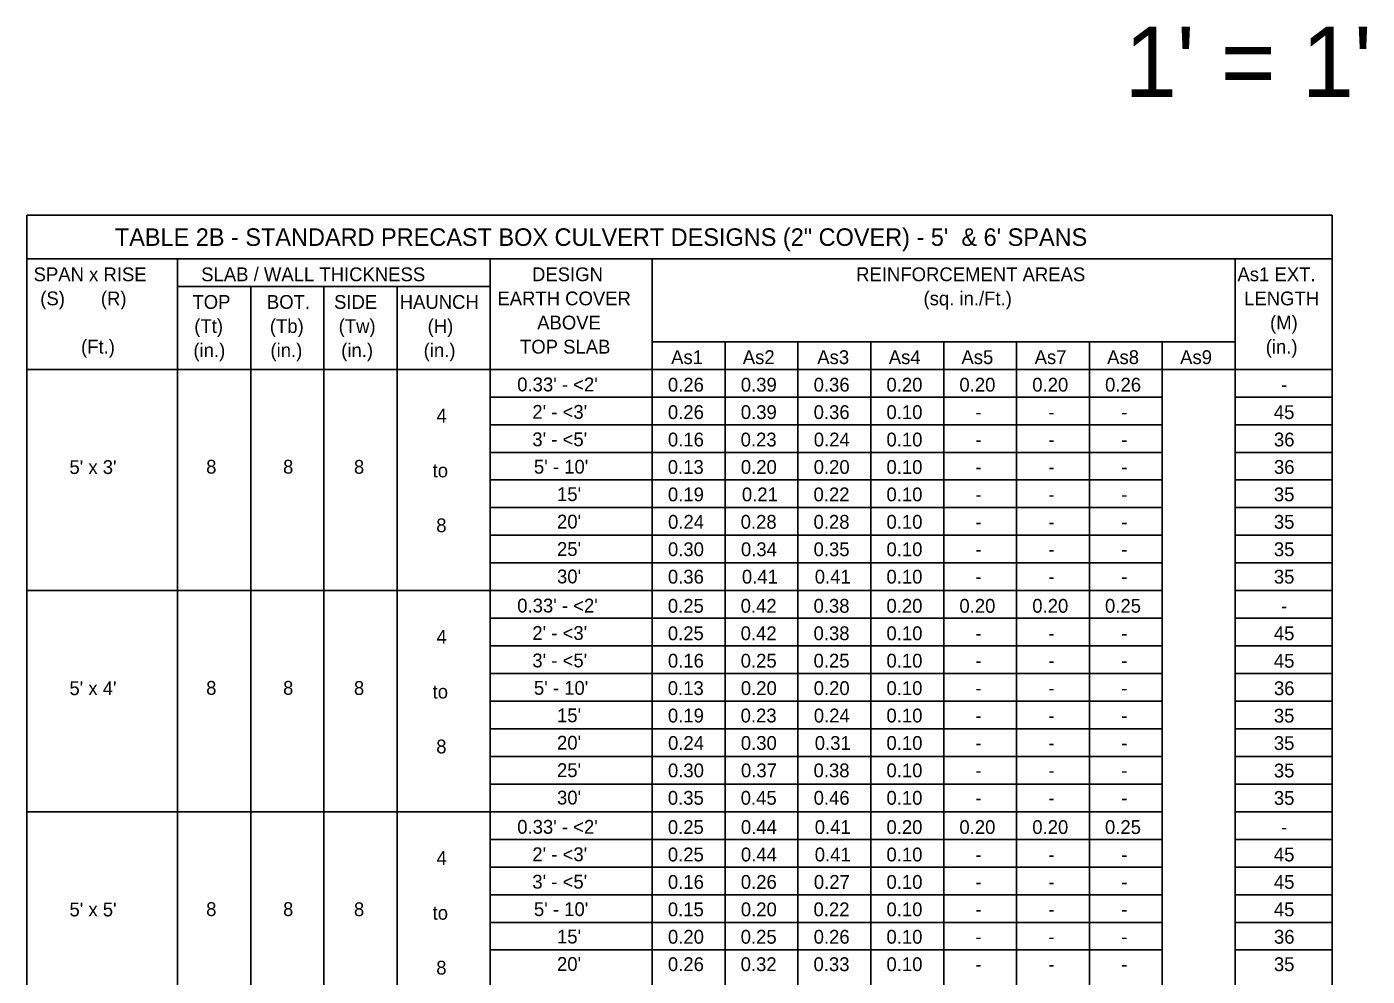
# Model space of a CAD drawing. Extents: x 10340.93 to 10343.14, y 76399.51 to 76400.59.
# Drawn here: x 10341.579 to 10342.189, y 76400.153 to 76400.586 of the extents above; entities that cross this region are included whole.
import ezdxf

# ---------------------------------------------------------------- set-up
doc = ezdxf.new("R2010")
doc.units = 0
doc.layers.add('AdhocPoint_dp', color=7, linetype='Continuous')
doc.layers.add('PlotBorder_dp', color=7, linetype='Continuous')

msp = doc.modelspace()

# ---------------------------------------------------------------- linework, layer by layer
at = {"layer": 'PlotBorder_dp'}
for p, q in [((10341.57868, 76400.49971), (10341.57868, 76399.72389)), ((10341.57868, 76400.49971), (10342.17342, 76400.49971)), ((10342.17342, 76400.49971), (10342.17342, 76399.72389)), ((10341.57868, 76400.47984), (10342.17342, 76400.47984)), ((10341.64732, 76400.47984), (10341.64732, 76399.72389)), ((10341.78976, 76400.47984), (10341.78976, 76399.72389)), ((10341.86364, 76400.47984), (10341.86364, 76399.72389)), ((10342.12923, 76400.47984), (10342.12923, 76399.72389)), ((10341.64732, 76400.46724), (10341.78976, 76400.46724)), ((10341.68068, 76400.46724), (10341.68068, 76399.72389)), ((10341.71404, 76400.46724), (10341.71404, 76399.72389)), ((10341.7474, 76400.46724), (10341.7474, 76399.72389)), ((10341.86364, 76400.44209), (10342.12923, 76400.44209)), ((10341.89684, 76400.44209), (10341.89684, 76399.72389)), ((10341.93004, 76400.44209), (10341.93004, 76399.72389)), ((10341.96324, 76400.44209), (10341.96324, 76399.72389)), ((10341.99644, 76400.44209), (10341.99644, 76399.72389)), ((10342.02963, 76400.44209), (10342.02963, 76399.72389)), ((10342.02963, 76400.44209), (10342.02963, 76399.72389)), ((10342.06283, 76400.44209), (10342.06283, 76399.72389)), ((10342.09603, 76400.44209), (10342.09603, 76399.72389)), ((10341.57868, 76400.42949), (10342.17342, 76400.42949)), ((10341.78976, 76400.41689), (10342.09603, 76400.41689)), ((10342.12923, 76400.41689), (10342.17342, 76400.41689)), ((10341.78976, 76400.40429), (10342.09603, 76400.40429)), ((10342.12923, 76400.40429), (10342.17342, 76400.40429)), ((10341.78976, 76400.39169), (10342.09603, 76400.39169)), ((10342.12923, 76400.39169), (10342.17342, 76400.39169)), ((10341.78976, 76400.37909), (10342.09603, 76400.37909)), ((10342.12923, 76400.37909), (10342.17342, 76400.37909)), ((10341.78976, 76400.36649), (10342.09603, 76400.36649)), ((10342.12923, 76400.36649), (10342.17342, 76400.36649)), ((10341.78976, 76400.35389), (10342.09603, 76400.35389)), ((10342.12923, 76400.35389), (10342.17342, 76400.35389)), ((10341.78976, 76400.34129), (10342.09603, 76400.34129)), ((10342.12923, 76400.34129), (10342.17342, 76400.34129)), ((10341.57868, 76400.32869), (10342.09603, 76400.32869)), ((10342.12923, 76400.32869), (10342.17342, 76400.32869)), ((10341.78976, 76400.31609), (10342.09603, 76400.31609)), ((10342.12923, 76400.31609), (10342.17342, 76400.31609)), ((10341.78976, 76400.30349), (10342.09603, 76400.30349)), ((10342.12923, 76400.30349), (10342.17342, 76400.30349)), ((10341.78976, 76400.29089), (10342.09603, 76400.29089)), ((10342.12923, 76400.29089), (10342.17342, 76400.29089)), ((10341.78976, 76400.27829), (10342.09603, 76400.27829)), ((10342.12923, 76400.27829), (10342.17342, 76400.27829)), ((10341.78976, 76400.26569), (10342.09603, 76400.26569)), ((10342.12923, 76400.26569), (10342.17342, 76400.26569)), ((10341.78976, 76400.25309), (10342.09603, 76400.25309)), ((10342.12923, 76400.25309), (10342.17342, 76400.25309)), ((10341.78976, 76400.24049), (10342.09603, 76400.24049)), ((10342.12923, 76400.24049), (10342.17342, 76400.24049)), ((10341.57868, 76400.22789), (10342.09603, 76400.22789)), ((10342.12923, 76400.22789), (10342.17342, 76400.22789)), ((10341.78976, 76400.21529), (10342.09603, 76400.21529)), ((10342.12923, 76400.21529), (10342.17342, 76400.21529)), ((10341.78976, 76400.20269), (10342.09603, 76400.20269)), ((10342.12923, 76400.20269), (10342.17342, 76400.20269)), ((10341.78976, 76400.19009), (10342.09603, 76400.19009)), ((10342.12923, 76400.19009), (10342.17342, 76400.19009)), ((10341.78976, 76400.17749), (10342.09603, 76400.17749)), ((10342.12923, 76400.17749), (10342.17342, 76400.17749)), ((10341.78976, 76400.16489), (10342.09603, 76400.16489)), ((10342.12923, 76400.16489), (10342.17342, 76400.16489))]:
    msp.add_line(p, q, dxfattribs=at)

# ---------------------------------------------------------------- texts
at = {"layer": 'AdhocPoint_dp'}
for s, height, p in [("1' = 1'", 0.032, (10342.07883, 76400.55363)), ('TABLE 2B - STANDARD PRECAST BOX CULVERT DESIGNS (2" COVER) - 5\'  & 6\' SPANS', 0.008, (10341.6188, 76400.48578)), ('SLAB / WALL THICKNESS', 0.0063, (10341.65814, 76400.46968)), ('As1', 0.0063, (10341.87226, 76400.43192)), ('As2', 0.0063, (10341.90489, 76400.43192)), ('As3', 0.0063, (10341.93883, 76400.43192)), ('As4', 0.0063, (10341.97141, 76400.43192)), ('As5', 0.0063, (10342.00451, 76400.43192)), ('As7', 0.0063, (10342.03786, 76400.43192)), ('As8', 0.0063, (10342.0709, 76400.43192)), ('As9', 0.0063, (10342.10415, 76400.43192)), ("5' x 3'", 0.0063, (10341.5981, 76400.38182)), ("5' x 4'", 0.0063, (10341.59809, 76400.28104)), ("5' x 5'", 0.0063, (10341.59811, 76400.18021))]:
    msp.add_text(s, height=height, dxfattribs=at).set_placement(p)
at = {"layer": 'PlotBorder_dp'}
for s, p in [('SPAN x RISE', (10341.58177, 76400.46969)), ('DESIGN', (10341.80886, 76400.46969)), ('REINFORCEMENT AREAS', (10341.95654, 76400.46969)), ('(S)       (R)', (10341.58481, 76400.45869)), ('EARTH COVER', (10341.79307, 76400.45869)), ('(sq. in./Ft.)', (10341.98723, 76400.45869)), ('TOP', (10341.65414, 76400.45708)), ('BOT.', (10341.68807, 76400.45708)), ('SIDE', (10341.71867, 76400.45708)), ('HAUNCH', (10341.74856, 76400.45708)), ('(Tt)', (10341.65498, 76400.44608)), ('(Tb)', (10341.68941, 76400.44608)), ('(Tw)', (10341.72077, 76400.44608)), ('(H)', (10341.7613, 76400.44608)), ('ABOVE', (10341.81121, 76400.44769)), ('(Ft.)', (10341.60339, 76400.43669)), ('(in.)', (10341.65459, 76400.43508)), ('(in.)', (10341.68969, 76400.43508)), ('(in.)', (10341.72192, 76400.43508)), ('(in.)', (10341.75949, 76400.43508)), ('TOP SLAB', (10341.80338, 76400.43669)), ("0.33' - <2'", (10341.80212, 76400.41948)), ('0.26', (10341.87078, 76400.41937)), ('0.39', (10341.90398, 76400.41937)), ('0.36', (10341.93718, 76400.41937)), ('0.20', (10341.97035, 76400.41937)), ('0.20', (10342.00358, 76400.41937)), ('0.20', (10342.03679, 76400.41937)), ('0.26', (10342.06996, 76400.41937)), ('-', (10342.15015, 76400.41937)), ('4', (10341.76534, 76400.40529)), ("2' - <3'", (10341.80901, 76400.40698)), ('0.26', (10341.87078, 76400.40687)), ('0.39', (10341.90398, 76400.40687)), ('0.36', (10341.93718, 76400.40687)), ('0.10', (10341.97035, 76400.40687)), ('-', (10342.01091, 76400.40687)), ('-', (10342.04412, 76400.40687)), ('-', (10342.0773, 76400.40687)), ('45', (10342.14685, 76400.40687)), ("3' - <5'", (10341.80901, 76400.39448)), ('0.16', (10341.87078, 76400.39437)), ('0.23', (10341.90391, 76400.39437)), ('0.24', (10341.93724, 76400.39437)), ('0.10', (10341.97035, 76400.39437)), ('-', (10342.01091, 76400.39437)), ('-', (10342.04412, 76400.39437)), ('-', (10342.0773, 76400.39437)), ('36', (10342.14689, 76400.39437)), ('8', (10341.66039, 76400.38198)), ('8', (10341.69543, 76400.38198)), ('8', (10341.72772, 76400.38193)), ('to', (10341.76356, 76400.38029)), ("5' - 10'", (10341.80973, 76400.38198)), ('0.13', (10341.87071, 76400.38187)), ('0.20', (10341.90399, 76400.38187)), ('0.20', (10341.93719, 76400.38187)), ('0.10', (10341.97035, 76400.38187)), ('36', (10342.14689, 76400.38187)), ('-', (10342.01091, 76400.38187)), ('-', (10342.04412, 76400.38187)), ('-', (10342.0773, 76400.38187)), ("15'", (10341.82025, 76400.36948)), ('0.19', (10341.87078, 76400.36937)), ('0.21', (10341.90448, 76400.36937)), ('0.22', (10341.93712, 76400.36937)), ('0.10', (10341.97035, 76400.36937)), ('35', (10342.14685, 76400.36937)), ('-', (10342.01091, 76400.36937)), ('-', (10342.04412, 76400.36937)), ('-', (10342.0773, 76400.36937)), ('8', (10341.76523, 76400.35529)), ("20'", (10341.82025, 76400.35698)), ('0.24', (10341.87084, 76400.35687)), ('0.28', (10341.90393, 76400.35687)), ('0.28', (10341.93713, 76400.35687)), ('0.10', (10341.97035, 76400.35687)), ('35', (10342.14685, 76400.35687)), ('-', (10342.01091, 76400.35687)), ('-', (10342.04412, 76400.35687)), ('-', (10342.0773, 76400.35687)), ("25'", (10341.82025, 76400.34448)), ('0.30', (10341.8708, 76400.34437)), ('0.34', (10341.90404, 76400.34437)), ('0.35', (10341.93714, 76400.34437)), ('0.10', (10341.97035, 76400.34437)), ('35', (10342.14685, 76400.34437)), ('-', (10342.01091, 76400.34437)), ('-', (10342.04412, 76400.34437)), ('-', (10342.0773, 76400.34437)), ("30'", (10341.82025, 76400.33198)), ('0.36', (10341.87078, 76400.33187)), ('0.41', (10341.90448, 76400.33187)), ('0.41', (10341.93768, 76400.33187)), ('0.10', (10341.97035, 76400.33187)), ('35', (10342.14685, 76400.33187)), ('-', (10342.01091, 76400.33187)), ('-', (10342.04412, 76400.33187)), ('-', (10342.0773, 76400.33187)), ("0.33' - <2'", (10341.80212, 76400.3187)), ('0.25', (10341.87074, 76400.31859)), ('0.42', (10341.90392, 76400.31859)), ('0.38', (10341.93713, 76400.31859)), ('0.20', (10341.97035, 76400.31859)), ('0.20', (10342.00358, 76400.31859)), ('0.20', (10342.03679, 76400.31859)), ('0.25', (10342.06992, 76400.31859)), ('-', (10342.15015, 76400.31854)), ("2' - <3'", (10341.80901, 76400.3062)), ('0.25', (10341.87074, 76400.30609)), ('0.42', (10341.90392, 76400.30609)), ('0.38', (10341.93713, 76400.30609)), ('0.10', (10341.97035, 76400.30609)), ('45', (10342.14685, 76400.30604)), ('4', (10341.76534, 76400.30449)), ('-', (10342.01091, 76400.30609)), ('-', (10342.04412, 76400.30609)), ('-', (10342.0773, 76400.30609)), ("3' - <5'", (10341.80901, 76400.2937)), ('0.16', (10341.87078, 76400.29359)), ('0.25', (10341.90394, 76400.29359)), ('0.25', (10341.93714, 76400.29359)), ('0.10', (10341.97035, 76400.29359)), ('45', (10342.14685, 76400.29354)), ('-', (10342.01091, 76400.29359)), ('-', (10342.04412, 76400.29359)), ('-', (10342.0773, 76400.29359)), ('8', (10341.66039, 76400.2812)), ('8', (10341.69543, 76400.2812)), ('8', (10341.72772, 76400.28114)), ("5' - 10'", (10341.80973, 76400.2812)), ('0.13', (10341.87071, 76400.28109)), ('0.20', (10341.90399, 76400.28109)), ('0.20', (10341.93719, 76400.28109)), ('0.10', (10341.97035, 76400.28109)), ('36', (10342.14689, 76400.28104)), ('to', (10341.76356, 76400.27949)), ('-', (10342.01091, 76400.28109)), ('-', (10342.04412, 76400.28109)), ('-', (10342.0773, 76400.28109)), ("15'", (10341.82025, 76400.2687)), ('0.19', (10341.87078, 76400.26859)), ('0.23', (10341.90391, 76400.26859)), ('0.24', (10341.93724, 76400.26859)), ('0.10', (10341.97035, 76400.26859)), ('-', (10342.01091, 76400.26859)), ('-', (10342.04412, 76400.26859)), ('-', (10342.0773, 76400.26859)), ('35', (10342.14685, 76400.26854)), ('8', (10341.76523, 76400.25449)), ("20'", (10341.82025, 76400.2562)), ('0.24', (10341.87084, 76400.25609)), ('0.30', (10341.90399, 76400.25609)), ('0.31', (10341.93768, 76400.25609)), ('0.10', (10341.97035, 76400.25609)), ('-', (10342.01091, 76400.25609)), ('-', (10342.04412, 76400.25609)), ('-', (10342.0773, 76400.25609)), ('35', (10342.14685, 76400.25604)), ("25'", (10341.82025, 76400.2437)), ('0.30', (10341.8708, 76400.24359)), ('0.37', (10341.90406, 76400.24359)), ('0.38', (10341.93713, 76400.24359)), ('0.10', (10341.97035, 76400.24359)), ('-', (10342.01091, 76400.24359)), ('-', (10342.04412, 76400.24359)), ('-', (10342.0773, 76400.24359)), ('35', (10342.14685, 76400.24354)), ("30'", (10341.82025, 76400.2312)), ('0.35', (10341.87074, 76400.23109)), ('0.45', (10341.90394, 76400.23109)), ('0.46', (10341.93718, 76400.23109)), ('0.10', (10341.97035, 76400.23109)), ('-', (10342.01091, 76400.23109)), ('-', (10342.04412, 76400.23109)), ('-', (10342.0773, 76400.23109)), ('35', (10342.14685, 76400.23104)), ("0.33' - <2'", (10341.80212, 76400.21786)), ('0.25', (10341.87074, 76400.21776)), ('0.44', (10341.90404, 76400.21776)), ('0.41', (10341.93768, 76400.21776)), ('0.20', (10341.97035, 76400.21776)), ('0.20', (10342.00358, 76400.21776)), ('0.20', (10342.03679, 76400.21776)), ('0.25', (10342.06992, 76400.21776)), ('-', (10342.15015, 76400.21776)), ('4', (10341.76534, 76400.20369)), ("2' - <3'", (10341.80901, 76400.20536)), ('0.25', (10341.87074, 76400.20526)), ('0.44', (10341.90404, 76400.20526)), ('0.41', (10341.93768, 76400.20526)), ('0.10', (10341.97035, 76400.20526)), ('-', (10342.01091, 76400.20526)), ('-', (10342.04412, 76400.20526)), ('-', (10342.0773, 76400.20526)), ('45', (10342.14685, 76400.20526)), ("3' - <5'", (10341.80901, 76400.19286)), ('0.16', (10341.87078, 76400.19276)), ('0.26', (10341.90398, 76400.19276)), ('0.27', (10341.93726, 76400.19276)), ('0.10', (10341.97035, 76400.19276)), ('45', (10342.14685, 76400.19276)), ('-', (10342.01091, 76400.19276)), ('-', (10342.04412, 76400.19276)), ('-', (10342.0773, 76400.19276)), ('8', (10341.66039, 76400.18036)), ('8', (10341.69543, 76400.18036)), ('8', (10341.72772, 76400.18031)), ('to', (10341.76356, 76400.17869)), ("5' - 10'", (10341.80973, 76400.18036)), ('0.15', (10341.87074, 76400.18026)), ('0.20', (10341.90399, 76400.18026)), ('0.22', (10341.93712, 76400.18026)), ('0.10', (10341.97035, 76400.18026)), ('45', (10342.14685, 76400.18026)), ('-', (10342.01091, 76400.18026)), ('-', (10342.04412, 76400.18026)), ('-', (10342.0773, 76400.18026)), ("15'", (10341.82025, 76400.16786)), ('0.20', (10341.8708, 76400.16776)), ('0.25', (10341.90394, 76400.16776)), ('0.26', (10341.93718, 76400.16776)), ('0.10', (10341.97035, 76400.16776)), ('36', (10342.14689, 76400.16776)), ('-', (10342.01091, 76400.16776)), ('-', (10342.04412, 76400.16776)), ('-', (10342.0773, 76400.16776)), ('8', (10341.76523, 76400.15369)), ("20'", (10341.82025, 76400.15536)), ('0.26', (10341.87078, 76400.15526)), ('0.32', (10341.90392, 76400.15526)), ('0.33', (10341.93711, 76400.15526)), ('0.10', (10341.97035, 76400.15526)), ('35', (10342.14685, 76400.15526)), ('-', (10342.01091, 76400.15526)), ('-', (10342.04412, 76400.15526)), ('-', (10342.0773, 76400.15526))]:
    msp.add_text(s, height=0.0063, dxfattribs=at).set_placement(p)
for s, p in [('As1 EXT.', (10342.13028, 76400.46969)), ('LENGTH', (10342.1333, 76400.45869)), ('(M)', (10342.14511, 76400.44769)), ('(in.)', (10342.14315, 76400.43669))]:
    msp.add_text(s, height=0.0063, rotation=360, dxfattribs=at).set_placement(p)

doc.saveas('drawing.dxf')
